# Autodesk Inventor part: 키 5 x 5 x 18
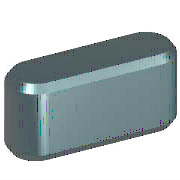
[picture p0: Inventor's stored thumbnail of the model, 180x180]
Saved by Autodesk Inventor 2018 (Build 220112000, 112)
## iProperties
Created: 2012-02
Part Number: 키 5 x 5 x 18
Material: 강철, 연강
Description: 키 및 해당 키홈
Document SubType Name: Modeling
Standard: KS B 1311
Designer: mduedu
Standards Organization: KS
Language: ko-KR
Size Designation: 5 x 5 x 18
Categories: <MemberInstance><Categories><Category DisplayName="샤프트 부품" InternalName="7f7aeb1f-a693-4053-b835-cee3144e0d98" Mnemonic="SHFT"><Category DisplayName="키" Interna
Density: 7.86 g/cm^3
Mass: 3.27476 g
Surface Area: 3.57848 cm^2
Volume: 0.416636 cm^3
Appearance: 노란색
IsCustomPart: 1
Author: mduedu
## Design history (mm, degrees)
workplane "Work Plane1"
workplane "Work Plane2"
sketch "스케치1"
  geometry: L1 (2.5, 2.5)-(15.5, 2.5); L2 (15.5, -2.5)-(2.5, -2.5); L3 (0, 9.4)-(0, -7.4) reference; L4 (-5, 0)-(30, 0) reference; L5 (18, 0)-(18, 7); A1 r 2.5 centre (2.5, 0) between (2.5, 2.5) and (2.5, -2.5); A2 r 2.5 centre (15.5, 0) between (15.5, -2.5) and (15.5, 2.5)
  constraints: 6 end point, 5 point on circle, 4 tangent, 3 point on line, 2 centre point, 1 horizontal, 1 parallel, 1 perpendicular
  dimensions: "d0" = 2.5 radius of A1 (= 0.5 x PB); "d13" = 2.5 radius of A2 (= 0.5 x PB); "d14" = 18 distance between parallel lines of L5 L3 (= NLG)
extrude "본체1" new body sketch "스케치1" taper "d3" = 0 deg; stored distance "d4" = 10
workplane "Work Plane3"
body "Solid1"
chamfer "모따기1" distance "d8" = 0.4 (= PHH); stored, may be unused: second distance "d9" = 0.4 (= PHH), angle "d15" = 45 deg
other parameters: "d1" = -3 (= -PNT), "d2" = 2 (= PH - PNT), "NLG" = 18 [user parameter; used in 3 equation terms], "PB" = 5 [user parameter; used in 2 equation terms], "PNT" = 3 [user parameter; used in 2 equation terms], "PH" = 5 [user parameter; used in 1 equation term], "PHH" = 0.4 [user parameter; used in 2 equation terms], "d10" = 0, "d16" = 0, "d17" = 0, "d18" = 0, "WDMIN" = 12 [user parameter], "PLB2" = 18 (= NLG) [user parameter], "WDMAX" = 17 [user parameter], "PLB1" = 18 (= NLG) [user parameter], "RR" = 0.16 [user parameter], "PUEB" = 2.3 [user parameter]
